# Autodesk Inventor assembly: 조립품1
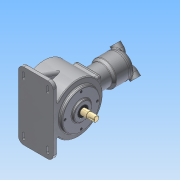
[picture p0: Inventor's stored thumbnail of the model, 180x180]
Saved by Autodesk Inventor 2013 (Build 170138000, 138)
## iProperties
Created: 2015-06
Part Number: 조립품1
Document SubType Name: Assembly
Designer: ST
Author: ST
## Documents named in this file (15)
- C:\Users\ST\Desktop\450605v1054\조립품1.iam
- C:\Users\ST\Desktop\450605v1054\본체.ipt
- C:\Users\ST\Desktop\450605v1054\메인 크랭크 축-구동부.ipt
- C:\Users\ST\Desktop\450605v1054\메인커버.ipt
- C:\Users\ST\Desktop\450605v1054\베어링 NA 4902.ipt
- C:\Users\ST\Desktop\450605v1054\실린더.ipt
- C:\Users\ST\Desktop\450605v1054\실린더헤드.ipt
- C:\Users\ST\Desktop\450605v1054\오일실.ipt
- C:\Users\ST\Desktop\450605v1054\커넥팅 로드.ipt
- C:\Users\ST\Desktop\450605v1054\크랭크 서브축.ipt
- C:\Users\ST\Desktop\450605v1054\피스톤 핀.ipt
- C:\Users\ST\Desktop\450605v1054\피스톤.ipt
- C:\Users\ST\Desktop\450605v1054\베어링 6204.ipt
- C:\Users\ST\Desktop\450605v1054\M4x0.7.ipt
- C:\Users\ST\Desktop\450605v1054\M5x0.8.ipt
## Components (14 placed, 4 different names)
1. 피스톤 핀:1
2. 피스톤:1
3. M5x0.8:1 — 각도:2
4. M5x0.8:2
5. M5x0.8:3
6. M5x0.8:4
7. M4x0.7:1 — 각도:3
8. M4x0.7:3
9. M4x0.7:4
10. M4x0.7:5
11. M4x0.7:2 — 각도:4
12. M4x0.7:6
13. M4x0.7:7
14. M4x0.7:8
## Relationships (3: Angle 3)
- 각도:2 [Angle]: M5x0.8:1
- 각도:3 [Angle]: M4x0.7:1
- 각도:4 [Angle]: M4x0.7:2
